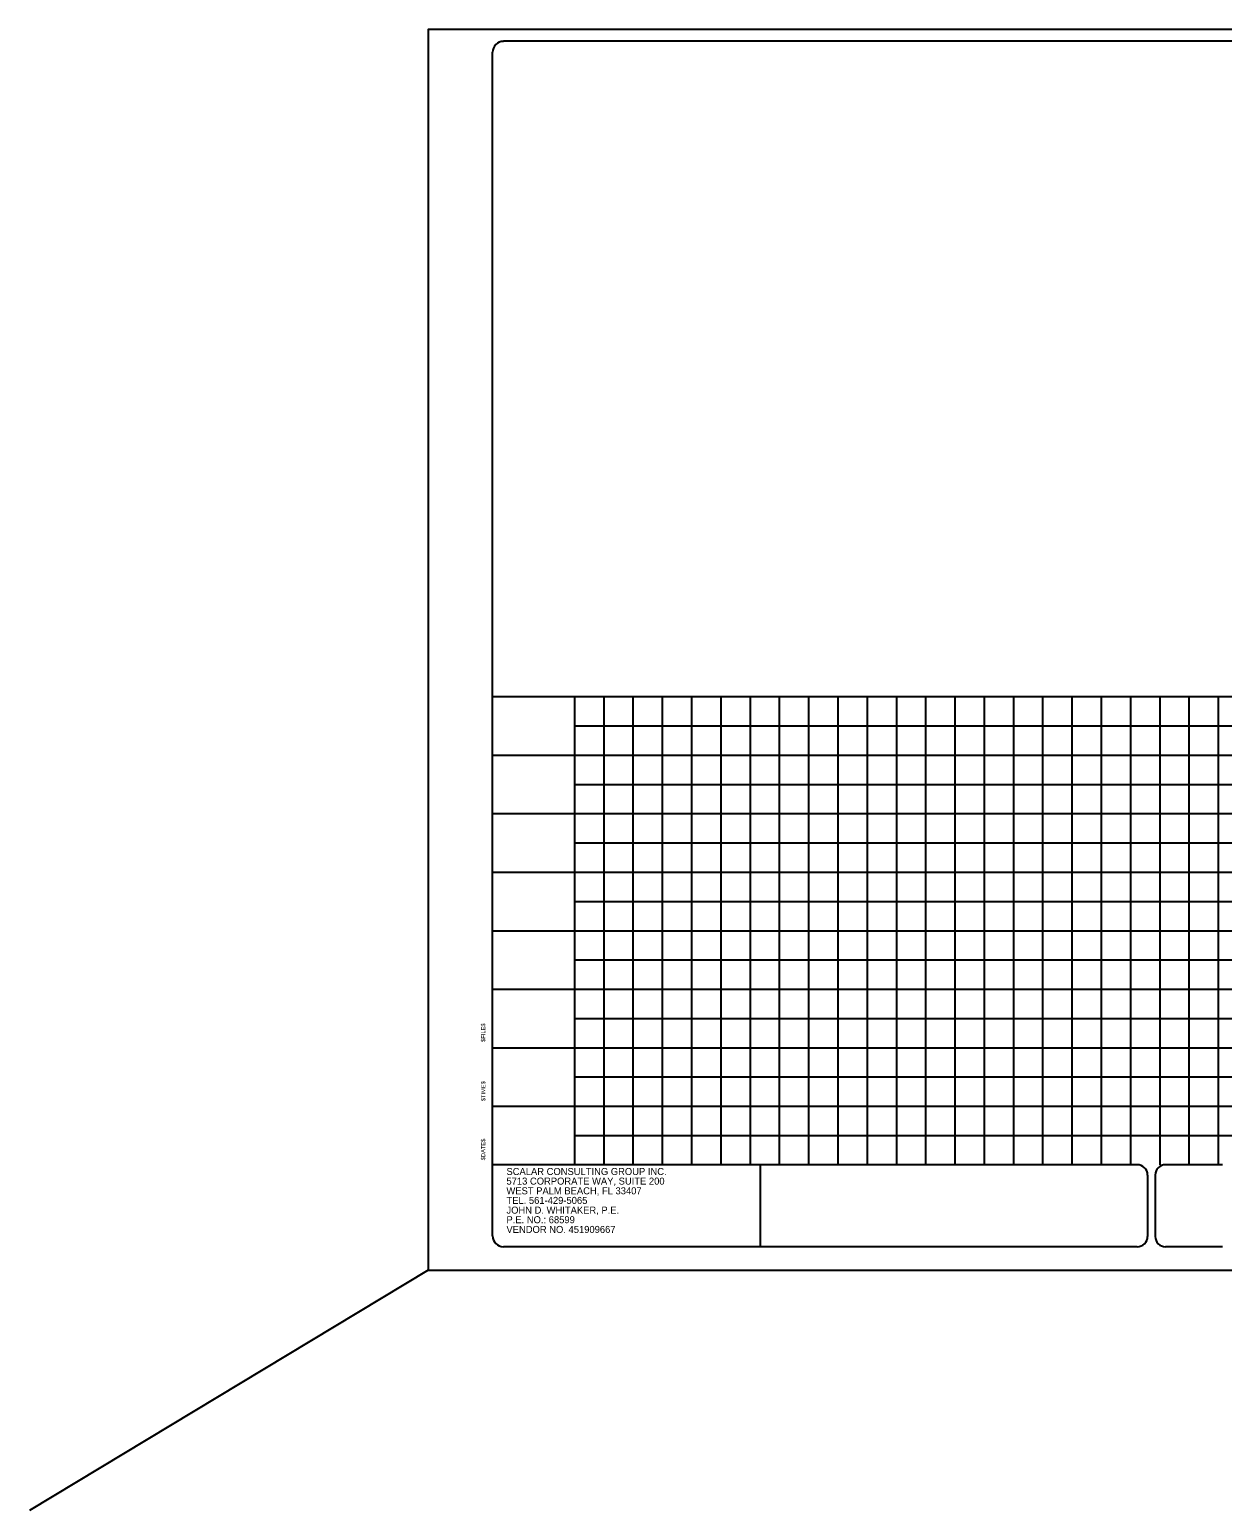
# Model space of a CAD drawing. Extents: x -4 to 16, y -3 to 9.7.
# Drawn here: x -3.95 to 6.24, y -2.95 to 9.7 of the extents above; entities that cross this region are included whole.
import ezdxf

# ---------------------------------------------------------------- set-up
doc = ezdxf.new("R2010")
doc.units = 0
for name, color, linetype in [('Baseline Bearing and Curve Data', 7, 'Continuous'), ('Baseline Station and Tick Mark', 7, 'Continuous'), ('Centerline (Construction)', 7, 'Continuous'), ('Default', 7, 'Continuous'), ('Property Corners', 7, 'Continuous')]:
    doc.layers.add(name, color=color, linetype=linetype)

msp = doc.modelspace()

# ---------------------------------------------------------------- linework, layer by layer
at = {"layer": 'Baseline Bearing and Curve Data'}
for p, q in [((0.7, 4), (0.7, 0)), ((1.2, 4), (1.2, 0)), ((1.7, 4), (1.7, 0)), ((2.2, 4), (2.2, 0)), ((2.7, 4), (2.7, 0)), ((3.2, 4), (3.2, 0)), ((3.7, 4), (3.7, 0)), ((4.2, 4), (4.2, 0)), ((4.7, 4), (4.7, 0)), ((5.2, 4), (5.2, 0)), ((5.7, 4), (5.7, 0)), ((6.2, 4), (6.2, 0)), ((0, 3.5), (15.4, 3.5)), ((0, 3), (15.4, 3)), ((0, 2.5), (15.4, 2.5)), ((0, 2), (15.4, 2)), ((0, 1.5), (15.4, 1.5)), ((0, 1), (15.4, 1)), ((0, 0.5), (15.4, 0.5))]:
    msp.add_line(p, q, dxfattribs=at)
at = {"layer": 'Baseline Station and Tick Mark'}
msp.add_line((0, 4), (15.4, 4), dxfattribs=at)
at = {"layer": 'Centerline (Construction)'}
msp.add_lwpolyline([(-0.55, -0.9), (15.95, -0.9), (15.95, 9.7), (-0.55, 9.7)], close=True, dxfattribs=at)
at = {"layer": 'Default'}
for p, q in [((0, -0.608), (0, 9.506)), ((15.325, 9.6), (0.094, 9.6)), ((5.508, 0), (0, 0)), ((6.236, 0), (5.75, 0)), ((2.289, -0.701), (2.289, 0)), ((5.596, -0.088), (5.596, -0.613)), ((5.662, -0.088), (5.662, -0.613)), ((5.508, -0.701), (0.093, -0.701)), ((6.236, -0.701), (5.75, -0.701)), ((-0.55, -0.9), (-3.955, -2.954))]:
    msp.add_line(p, q, dxfattribs=at)
for centre, major_axis, start_param, end_param in [((0.094, 9.506), (0, -0.0935), 3.141593, 4.712389), ((5.508, -0.088), (0, 0.0882), 4.712389, 6.283185), ((5.75, -0.088), (0, 0.0882), 0, 1.570796), ((0.094, -0.608), (0, -0.0935), 4.712389, 6.283185), ((5.508, -0.613), (0, 0.0882), 3.141593, 4.712389), ((5.75, -0.613), (0, -0.0882), 4.712389, 6.283185)]:
    msp.add_ellipse(centre, major_axis=major_axis, ratio=0.999927, start_param=start_param, end_param=end_param, dxfattribs=at)
at = {"layer": 'Property Corners'}
for p, q in [((0.95, 4), (0.95, 0)), ((1.45, 4), (1.45, 0)), ((1.95, 4), (1.95, 0)), ((2.45, 4), (2.45, 0)), ((2.95, 4), (2.95, 0)), ((3.45, 4), (3.45, 0)), ((3.95, 4), (3.95, 0)), ((4.45, 4), (4.45, 0)), ((4.95, 4), (4.95, 0)), ((5.45, 4), (5.45, 0)), ((5.95, 4), (5.95, 0)), ((0.7, 3.75), (14.7, 3.75)), ((0.7, 3.25), (14.7, 3.25)), ((0.7, 2.75), (14.7, 2.75)), ((0.7, 2.25), (14.7, 2.25)), ((0.7, 1.75), (14.7, 1.75)), ((0.7, 1.25), (14.7, 1.25)), ((0.7, 0.75), (14.7, 0.75)), ((0.7, 0.25), (14.7, 0.25))]:
    msp.add_line(p, q, dxfattribs=at)

# ---------------------------------------------------------------- texts
at = {"layer": 'Default'}
for s, p in [('$FILE$', (-0.062, 1.05)), ('$TIME$', (-0.061, 0.543)), ('$DATE$', (-0.062, 0.038))]:
    msp.add_text(s, height=0.0354, rotation=90, dxfattribs=at).set_placement(p)
for s, p in [('SCALAR CONSULTING GROUP INC.', (0.119, -0.088)), ('5713 CORPORATE WAY, SUITE 200', (0.119, -0.17)), ('WEST PALM BEACH, FL 33407', (0.119, -0.253)), ('TEL. 561-429-5065', (0.119, -0.335)), ('JOHN D. WHITAKER, P.E.', (0.119, -0.418)), ('P.E. NO.: 68599', (0.119, -0.5)), ('VENDOR NO. 451909667', (0.119, -0.583))]:
    msp.add_text(s, height=0.06, dxfattribs=at).set_placement(p)

doc.saveas('drawing.dxf')
